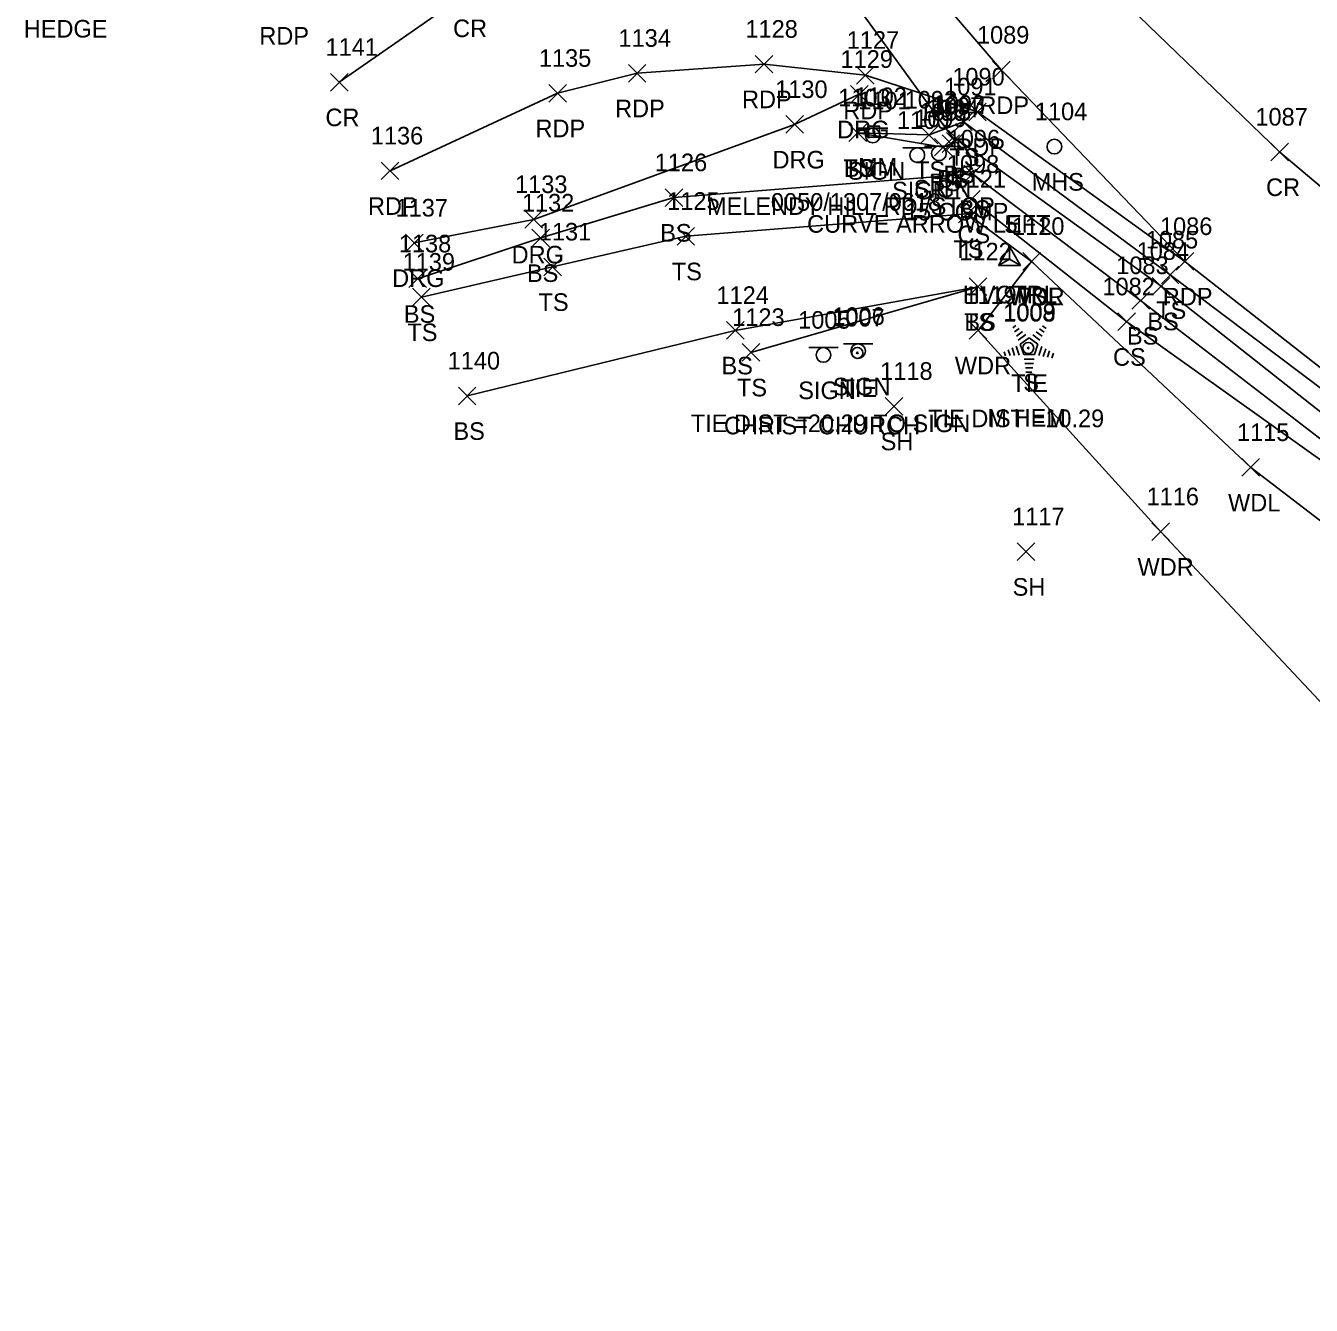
# Model space of a CAD drawing. Extents: x 1620157 to 1620595, y 115111 to 117885.
# Drawn here: x 1620296.4 to 1620442.4, y 115116.1 to 115261.5 of the extents above; entities that cross this region are included whole.
import ezdxf

# ---------------------------------------------------------------- set-up
doc = ezdxf.new("R2010")
doc.units = 0
for name, color, linetype in [('C_A', 7, 'Continuous'), ('C_C', 7, 'Continuous'), ('C_I', 7, 'Continuous'), ('CBP', 7, 'Continuous'), ('CPSM', 7, 'Continuous'), ('D_A', 7, 'Continuous'), ('D_C', 7, 'Continuous'), ('D_I', 7, 'Continuous'), ('D_TIC', 7, 'Continuous'), ('DCP', 7, 'Continuous'), ('L_A', 7, 'Continuous'), ('L_C', 7, 'Continuous'), ('L_I', 7, 'Continuous'), ('L_TIC', 7, 'Continuous'), ('LAWA', 7, 'Continuous'), ('LELB', 7, 'Continuous'), ('LTC', 7, 'Continuous'), ('P_A', 7, 'Continuous'), ('P_I', 7, 'Continuous'), ('P_TIC', 7, 'Continuous'), ('PET', 7, 'Continuous'), ('PRC', 7, 'Continuous'), ('R_A', 7, 'Continuous'), ('R_I', 7, 'Continuous'), ('R_TIC', 7, 'Continuous'), ('RDG', 7, 'Continuous'), ('S_A', 7, 'Continuous'), ('S_C', 7, 'Continuous'), ('S_I', 7, 'Continuous'), ('SRM', 7, 'Continuous'), ('SSGN', 7, 'Continuous'), ('U_A', 7, 'Continuous'), ('U_I', 7, 'Continuous'), ('USMH', 7, 'Continuous')]:
    doc.layers.add(name, color=color, linetype=linetype)

msp = doc.modelspace()

# ---------------------------------------------------------------- linework, layer by layer
at = {"layer": 'CBP'}
for centre, radius in [((1620390.83, 115224.31), 0.625), ((1620390.83, 115224.31), 0.0833), ((1620410.24, 115224.87), 0.625), ((1620410.24, 115224.87), 0.0833)]:
    msp.add_circle(centre, radius, dxfattribs=at)
at = {"layer": 'CPSM'}
for p, q in [((1620406.86, 115234.22), (1620408.11, 115236.39)), ((1620409.36, 115234.22), (1620408.11, 115236.39)), ((1620408.11, 115234.94), (1620408.11, 115236.39)), ((1620406.86, 115234.22), (1620408.11, 115234.94)), ((1620408.11, 115234.94), (1620408.11, 115234.94)), ((1620408.11, 115234.94), (1620409.36, 115234.22)), ((1620406.86, 115234.22), (1620409.36, 115234.22))]:
    msp.add_line(p, q, dxfattribs=at)
at = {"layer": 'D_TIC'}
for points in [[(1620400.96, 115247.35), (1620402.96, 115249.35)], [(1620402.96, 115247.35), (1620400.96, 115249.35)]]:
    msp.add_lwpolyline(points, dxfattribs=at)
at = {"layer": 'DCP'}
msp.add_lwpolyline([(1620401.96, 115248.35), (1620331.92, 115344.78)], dxfattribs=at)
at = {"layer": 'L_TIC'}
for points in [[(1620401.89, 115249.56), (1620403.89, 115251.56)], [(1620403.89, 115249.56), (1620401.89, 115251.56)], [(1620389.86, 115248.31), (1620391.86, 115250.31)], [(1620391.86, 115248.31), (1620389.86, 115250.31)], [(1620389.86, 115248.31), (1620391.86, 115250.31)], [(1620391.86, 115248.31), (1620389.86, 115250.31)], [(1620397.98, 115248.07), (1620399.98, 115250.07)], [(1620399.98, 115248.07), (1620397.98, 115250.07)], [(1620400.45, 115247.07), (1620402.45, 115249.07)], [(1620402.45, 115247.07), (1620400.45, 115249.07)], [(1620401.18, 115247.57), (1620403.18, 115249.57)], [(1620403.18, 115247.57), (1620401.18, 115249.57)], [(1620399.59, 115246.68), (1620401.59, 115248.68)], [(1620401.59, 115246.68), (1620399.59, 115248.68)], [(1620402.93, 115243.65), (1620404.93, 115245.65)], [(1620404.93, 115243.65), (1620402.93, 115245.65)], [(1620369, 115240.95), (1620371, 115242.95)], [(1620371, 115240.95), (1620369, 115242.95)], [(1620402.77, 115240.77), (1620404.77, 115242.77)], [(1620404.77, 115240.77), (1620402.77, 115242.77)], [(1620402.33, 115239.09), (1620404.33, 115241.09)], [(1620404.33, 115239.09), (1620402.33, 115241.09)], [(1620353.86, 115236.37), (1620355.86, 115238.37)], [(1620355.86, 115236.37), (1620353.86, 115238.37)], [(1620370.35, 115236.56), (1620372.35, 115238.56)], [(1620372.35, 115236.56), (1620370.35, 115238.56)], [(1620355.21, 115233.08), (1620357.21, 115235.08)], [(1620357.21, 115233.08), (1620355.21, 115235.08)], [(1620409.63, 115233.71), (1620411.63, 115235.71)], [(1620411.63, 115233.71), (1620409.63, 115235.71)], [(1620409.63, 115233.71), (1620411.63, 115235.71)], [(1620411.63, 115233.71), (1620409.63, 115235.71)], [(1620409.63, 115233.71), (1620411.63, 115235.71)], [(1620411.63, 115233.71), (1620409.63, 115235.71)], [(1620339.88, 115231.73), (1620341.88, 115233.73)], [(1620341.88, 115231.73), (1620339.88, 115233.73)], [(1620425.37, 115232.17), (1620427.37, 115234.17)], [(1620427.37, 115232.17), (1620425.37, 115234.17)], [(1620340.31, 115229.65), (1620342.31, 115231.65)], [(1620342.31, 115229.65), (1620340.31, 115231.65)], [(1620403.55, 115230.82), (1620405.55, 115232.82)], [(1620405.55, 115230.82), (1620403.55, 115232.82)], [(1620403.55, 115230.82), (1620405.55, 115232.82)], [(1620405.55, 115230.82), (1620403.55, 115232.82)], [(1620424.33, 115230.88), (1620426.33, 115232.88)], [(1620426.33, 115230.88), (1620424.33, 115232.88)], [(1620422.01, 115229.26), (1620424.01, 115231.26)], [(1620424.01, 115229.26), (1620422.01, 115231.26)], [(1620420.44, 115226.85), (1620422.44, 115228.85)], [(1620422.44, 115226.85), (1620420.44, 115228.85)], [(1620375.96, 115225.87), (1620377.96, 115227.87)], [(1620377.96, 115225.87), (1620375.96, 115227.87)], [(1620403.55, 115225.87), (1620405.55, 115227.87)], [(1620405.55, 115225.87), (1620403.55, 115227.87)], [(1620377.75, 115223.37), (1620379.75, 115225.37)], [(1620379.75, 115223.37), (1620377.75, 115225.37)], [(1620345.51, 115218.43), (1620347.51, 115220.43)], [(1620347.51, 115218.43), (1620345.51, 115220.43)], [(1620393.99, 115217.25), (1620395.99, 115219.25)], [(1620395.99, 115217.25), (1620393.99, 115219.25)], [(1620434.52, 115210.3), (1620436.52, 115212.3)], [(1620436.52, 115210.3), (1620434.52, 115212.3)], [(1620424.3, 115203), (1620426.3, 115205)], [(1620426.3, 115203), (1620424.3, 115205)], [(1620408.98, 115200.73), (1620410.98, 115202.73)], [(1620410.98, 115200.73), (1620408.98, 115202.73)]]:
    msp.add_lwpolyline(points, dxfattribs=at)
at = {"layer": 'LAWA'}
for points in [[(1620547.83, 115116.13), (1620521.54, 115127.07), (1620480.9, 115160.38), (1620453.76, 115173.69), (1620425.3, 115204), (1620404.55, 115226.87), (1620410.63, 115234.71)], [(1620557.01, 115131.08), (1620520.13, 115153.23), (1620496.39, 115166.83), (1620458.33, 115193.85), (1620435.52, 115211.3), (1620410.63, 115234.71)]]:
    msp.add_lwpolyline(points, dxfattribs=at)
at = {"layer": 'LELB'}
for points in [[(1620561.51, 115138.96), (1620534.96, 115155.05), (1620507.65, 115174.47), (1620478.57, 115195.13), (1620450.29, 115215.14), (1620426.37, 115233.17), (1620402.89, 115250.56), (1620398.98, 115249.07), (1620390.86, 115249.31)], [(1620561.16, 115138.52), (1620534.84, 115154.5), (1620507.17, 115173.96), (1620477.85, 115194.31), (1620448.7, 115213.47), (1620425.33, 115231.88), (1620402.18, 115248.57), (1620401.45, 115248.07), (1620400.59, 115247.68), (1620390.86, 115249.31)], [(1620560.42, 115137.14), (1620534.09, 115153.34), (1620505.73, 115171.81), (1620476.58, 115192.31), (1620447.1, 115211.71), (1620423.01, 115230.26), (1620403.93, 115244.65), (1620370, 115241.95), (1620354.86, 115237.37), (1620340.88, 115232.73)], [(1620559.1, 115135.33), (1620533.32, 115151.76), (1620504.7, 115169.78), (1620474.68, 115190.6), (1620444.93, 115211.09), (1620421.44, 115227.85), (1620403.77, 115241.77)], [(1620410.63, 115234.71), (1620403.33, 115240.09), (1620371.35, 115237.56), (1620356.21, 115234.08), (1620341.31, 115230.65)], [(1620404.55, 115231.82), (1620376.96, 115226.87), (1620346.51, 115219.43)], [(1620404.55, 115231.82), (1620378.75, 115224.37)]]:
    msp.add_lwpolyline(points, dxfattribs=at)
at = {"layer": 'LTC'}
for p, q in [((1620408.49, 115227.16), (1620408.84, 115227.41)), ((1620408.69, 115226.69), (1620409.22, 115227.07)), ((1620411.51, 115227.05), (1620412.06, 115226.65)), ((1620411.88, 115227.4), (1620412.3, 115227.09)), ((1620408.9, 115226.22), (1620409.61, 115226.74)), ((1620409.11, 115225.76), (1620409.99, 115226.4)), ((1620409.34, 115225.3), (1620410.35, 115226.04)), ((1620410.35, 115226.04), (1620411.35, 115225.31)), ((1620410.77, 115226.35), (1620411.58, 115225.76)), ((1620411.14, 115226.7), (1620411.82, 115226.21)), ((1620407.52, 115224.44), (1620407.67, 115223.97)), ((1620407.97, 115224.65), (1620408.18, 115224)), ((1620408.43, 115224.87), (1620408.7, 115224.03)), ((1620408.88, 115225.08), (1620409.21, 115224.07)), ((1620409.34, 115225.3), (1620409.73, 115224.11)), ((1620411.35, 115225.31), (1620410.96, 115224.11)), ((1620411.78, 115225.04), (1620411.45, 115224)), ((1620412.23, 115224.79), (1620411.94, 115223.91)), ((1620412.67, 115224.54), (1620412.44, 115223.81)), ((1620413.12, 115224.29), (1620412.93, 115223.72)), ((1620410.96, 115224.11), (1620409.73, 115224.11)), ((1620410.92, 115223.61), (1620409.77, 115223.61)), ((1620410.83, 115223.11), (1620409.85, 115223.11)), ((1620410.75, 115222.61), (1620409.92, 115222.61)), ((1620410.67, 115222.11), (1620409.99, 115222.11))]:
    msp.add_line(p, q, dxfattribs=at)
at = {"layer": 'P_TIC'}
for points in [[(1620379.24, 115256.11), (1620381.24, 115258.11)], [(1620381.24, 115256.11), (1620379.24, 115258.11)], [(1620364.82, 115255.08), (1620366.82, 115257.08)], [(1620366.82, 115255.08), (1620364.82, 115257.08)], [(1620390.75, 115254.85), (1620392.75, 115256.85)], [(1620392.75, 115254.85), (1620390.75, 115256.85)], [(1620406.2, 115255.44), (1620408.2, 115257.44)], [(1620408.2, 115255.44), (1620406.2, 115257.44)], [(1620330.98, 115254.06), (1620332.98, 115256.06)], [(1620332.98, 115254.06), (1620330.98, 115256.06)], [(1620355.78, 115252.81), (1620357.78, 115254.81)], [(1620357.78, 115252.81), (1620355.78, 115254.81)], [(1620403.48, 115250.68), (1620405.48, 115252.68)], [(1620405.48, 115250.68), (1620403.48, 115252.68)], [(1620437.82, 115246.13), (1620439.82, 115248.13)], [(1620439.82, 115246.13), (1620437.82, 115248.13)], [(1620336.75, 115243.99), (1620338.75, 115245.99)], [(1620338.75, 115243.99), (1620336.75, 115245.99)], [(1620427.04, 115233.7), (1620429.04, 115235.7)], [(1620429.04, 115233.7), (1620427.04, 115235.7)], [(1620427.04, 115233.7), (1620429.04, 115235.7)], [(1620429.04, 115233.7), (1620427.04, 115235.7)]]:
    msp.add_lwpolyline(points, dxfattribs=at)
at = {"layer": 'PET'}
for points in [[(1620562.04, 115139.54), (1620535.96, 115156.9), (1620508.49, 115175.94), (1620479.2, 115196.11), (1620451.1, 115216.62), (1620428.04, 115234.7), (1620407.2, 115256.44), (1620380.21, 115287.87), (1620366.18, 115309.19), (1620356.59, 115324.56), (1620350.49, 115341.93), (1620344.69, 115361.16), (1620336.51, 115388.61), (1620345.69, 115391.55), (1620355.3, 115394.86)], [(1620428.04, 115234.7), (1620404.48, 115251.68), (1620391.75, 115255.85), (1620380.24, 115257.11), (1620365.82, 115256.08), (1620356.78, 115253.81), (1620337.75, 115244.99)]]:
    msp.add_lwpolyline(points, dxfattribs=at)
at = {"layer": 'PRC'}
for points in [[(1620569.19, 115149.92), (1620542.76, 115168.02), (1620512.11, 115189.58), (1620491.05, 115205.01), (1620469.11, 115221.78), (1620461.73, 115227.82), (1620438.82, 115247.13), (1620418.59, 115266.65), (1620405.03, 115281.95), (1620392.88, 115297.86), (1620380.47, 115316.24), (1620370.64, 115332.81), (1620355.49, 115365.23), (1620348.1, 115384.58), (1620345.69, 115391.55)], [(1620331.98, 115255.06), (1620346.47, 115265.18), (1620365.55, 115277.69), (1620370.36, 115280.84), (1620377.45, 115285.52), (1620380.21, 115287.87)]]:
    msp.add_lwpolyline(points, dxfattribs=at)
at = {"layer": 'R_TIC'}
for points in [[(1620390.05, 115252.69), (1620392.05, 115254.69)], [(1620392.05, 115252.69), (1620390.05, 115254.69)], [(1620382.71, 115249.26), (1620384.71, 115251.26)], [(1620384.71, 115249.26), (1620382.71, 115251.26)], [(1620353.07, 115238.47), (1620355.07, 115240.47)], [(1620355.07, 115238.47), (1620353.07, 115240.47)], [(1620339.5, 115235.8), (1620341.5, 115237.8)], [(1620341.5, 115235.8), (1620339.5, 115237.8)]]:
    msp.add_lwpolyline(points, dxfattribs=at)
at = {"layer": 'RDG'}
msp.add_lwpolyline([(1620391.05, 115253.69), (1620383.71, 115250.26), (1620354.07, 115239.47), (1620340.5, 115236.8)], dxfattribs=at)
at = {"layer": 'SRM'}
msp.add_lwpolyline([(1620392.09, 115250.08), (1620393.34, 115250.08), (1620393.34, 115248.83), (1620392.09, 115248.83)], close=True, dxfattribs=at)
msp.add_circle((1620392.71, 115249.46), 0.0833, dxfattribs=at)
at = {"layer": 'SSGN'}
for p, q in [((1620390.95, 115249.83), (1620394.28, 115249.83)), ((1620392.59, 115249), (1620392.59, 115249)), ((1620395.99, 115247.6), (1620399.33, 115247.6)), ((1620398.45, 115247.81), (1620401.79, 115247.81)), ((1620397.64, 115246.77), (1620397.64, 115246.77)), ((1620400.1, 115246.98), (1620400.1, 115246.98)), ((1620385.33, 115224.91), (1620388.66, 115224.91)), ((1620389.27, 115225.34), (1620392.61, 115225.34)), ((1620390.92, 115224.51), (1620390.92, 115224.51)), ((1620386.98, 115224.08), (1620386.98, 115224.08))]:
    msp.add_line(p, q, dxfattribs=at)
for centre in [(1620392.59, 115249), (1620397.64, 115246.77), (1620400.1, 115246.98), (1620386.98, 115224.08), (1620390.92, 115224.51)]:
    msp.add_circle(centre, 0.833, dxfattribs=at)
at = {"layer": 'USMH'}
for p, q in [((1620413.21, 115247.74), (1620413.21, 115247.74)), ((1620414.04, 115247.74), (1620414.04, 115247.74))]:
    msp.add_line(p, q, dxfattribs=at)
msp.add_circle((1620413.21, 115247.74), 0.833, dxfattribs=at)

# ---------------------------------------------------------------- texts
at = {"layer": 'C_A'}
for s, p in [('HVCTRL', (1620402.81, 115229.94)), ('TIE', (1620388.91, 115219.31)), ('TIE', (1620408.32, 115219.87))]:
    msp.add_text(s, height=2, dxfattribs=at).set_placement(p)
at = {"layer": 'C_C'}
for s, p in [('TIE DIST =20.29 TO SIGN', (1620371.91, 115215.31)), ('TIE DIST =10.29', (1620398.88, 115215.87))]:
    msp.add_text(s, height=2, dxfattribs=at).set_placement(p)
at = {"layer": 'C_I'}
for s, p in [('5', (1620407.55, 115237.94)), ('1007', (1620387.98, 115227.31)), ('1008', (1620407.39, 115227.87))]:
    msp.add_text(s, height=2, dxfattribs=at).set_placement(p)
at = {"layer": 'D_A'}
msp.add_text('P', height=2, dxfattribs=at).set_placement((1620401.34, 115243.35))
at = {"layer": 'D_C'}
msp.add_text('15 CGMP', height=2, dxfattribs=at).set_placement((1620396.25, 115239.35))
at = {"layer": 'D_I'}
msp.add_text('1097', height=2, dxfattribs=at).set_placement((1620399.19, 115251.35))
at = {"layer": 'L_A'}
for s, p in [('HEDGE', (1620296.14, 115260.13)), ('TS', (1620401.3, 115245.56)), ('TS', (1620389.27, 115244.31)), ('BS', (1620389.3, 115244.31)), ('TS', (1620397.39, 115244.07)), ('BS', (1620399.03, 115242.68)), ('BS', (1620399.89, 115243.07)), ('BS', (1620400.62, 115243.57)), ('BS', (1620402.37, 115239.65)), ('BS', (1620368.44, 115236.95)), ('CS', (1620402.21, 115236.77)), ('TS', (1620401.74, 115235.09)), ('BS', (1620353.3, 115232.37)), ('TS', (1620369.76, 115232.56)), ('WDR', (1620407.99, 115229.71)), ('WDL', (1620408.04, 115229.71)), ('TS', (1620409.04, 115229.71)), ('TS', (1620354.62, 115229.08)), ('TS', (1620424.78, 115228.17)), ('BS', (1620339.32, 115227.73)), ('TS', (1620402.96, 115226.82)), ('BS', (1620402.99, 115226.82)), ('BS', (1620423.77, 115226.88)), ('TS', (1620339.72, 115225.65)), ('BS', (1620421.46, 115225.26)), ('CS', (1620419.88, 115222.85)), ('BS', (1620375.4, 115221.87)), ('WDR', (1620401.91, 115221.87)), ('TS', (1620377.16, 115219.37)), ('S', (1620409.68, 115219.95)), ('BS', (1620344.95, 115214.43)), ('SH', (1620393.48, 115213.25)), ('WDL', (1620432.94, 115206.3)), ('WDR', (1620422.66, 115199)), ('SH', (1620408.47, 115196.73))]:
    msp.add_text(s, height=2, dxfattribs=at).set_placement(p)
at = {"layer": 'L_C'}
msp.add_text('M HEM', height=2, dxfattribs=at).set_placement((1620405.61, 115215.95))
at = {"layer": 'L_I'}
for s, p in [('1091', (1620400.69, 115253.56)), ('1103', (1620388.66, 115252.31)), ('1103', (1620388.66, 115252.31)), ('1092', (1620396.21, 115252.07)), ('1093', (1620399.41, 115251.57)), ('1095', (1620397.82, 115250.68)), ('1094', (1620398.67, 115251.07)), ('1096', (1620401.1, 115247.65)), ('1126', (1620367.82, 115244.95)), ('1098', (1620401, 115244.77)), ('1121', (1620401.77, 115243.09)), ('1132', (1620352.73, 115240.37)), ('1125', (1620369.23, 115240.56)), ('1131', (1620354.65, 115237.08)), ('1120', (1620408.41, 115237.71)), ('1120', (1620408.41, 115237.71)), ('1120', (1620408.41, 115237.71)), ('1138', (1620338.75, 115235.73)), ('1085', (1620423.6, 115236.17)), ('1122', (1620402.42, 115234.82)), ('1122', (1620402.42, 115234.82)), ('1084', (1620422.56, 115234.88)), ('1139', (1620339.18, 115233.65)), ('1083', (1620420.24, 115233.26)), ('1124', (1620374.83, 115229.87)), ('1119', (1620402.98, 115229.87)), ('1082', (1620418.67, 115230.85)), ('1009', (1620407.43, 115227.95)), ('1123', (1620376.62, 115227.37)), ('1140', (1620344.3, 115222.43)), ('1118', (1620393.43, 115221.25)), ('1115', (1620433.96, 115214.3)), ('1116', (1620423.69, 115207)), ('1117', (1620408.42, 115204.73))]:
    msp.add_text(s, height=2, dxfattribs=at).set_placement(p)
at = {"layer": 'LTC'}
msp.add_text('.', height=1.04, rotation=270, dxfattribs=at).set_placement((1620410.23, 115225.05))
at = {"layer": 'P_A'}
for s, p in [('CR', (1620344.91, 115260.18)), ('RDP', (1620322.9, 115259.33)), ('RDP', (1620377.73, 115252.11)), ('RDP', (1620404.69, 115251.44)), ('CR', (1620330.41, 115250.06)), ('RDP', (1620363.31, 115251.08)), ('RDP', (1620389.24, 115250.85)), ('RDP', (1620354.27, 115248.81)), ('RDP', (1620401.96, 115246.68)), ('CR', (1620437.26, 115242.13)), ('RDP', (1620335.24, 115239.99)), ('RDP', (1620425.53, 115229.7)), ('RDP', (1620425.53, 115229.7))]:
    msp.add_text(s, height=2, dxfattribs=at).set_placement(p)
at = {"layer": 'P_I'}
for s, p in [('1128', (1620378.12, 115260.11)), ('1134', (1620363.7, 115259.08)), ('1127', (1620389.63, 115258.85)), ('1089', (1620404.42, 115259.44)), ('1141', (1620330.42, 115258.06)), ('1135', (1620354.66, 115256.81)), ('1090', (1620401.62, 115254.68)), ('1087', (1620436.05, 115250.13)), ('1136', (1620335.57, 115247.99)), ('1086', (1620425.21, 115237.7)), ('1086', (1620425.21, 115237.7))]:
    msp.add_text(s, height=2, dxfattribs=at).set_placement(p)
at = {"layer": 'R_A'}
for p in [(1620388.54, 115248.69), (1620381.2, 115245.26), (1620351.56, 115234.47), (1620337.99, 115231.8)]:
    msp.add_text('DRG', height=2, dxfattribs=at).set_placement(p)
at = {"layer": 'R_I'}
for s, p in [('1129', (1620388.92, 115256.69)), ('1130', (1620381.5, 115253.26)), ('1133', (1620351.95, 115242.47)), ('1137', (1620338.38, 115239.8))]:
    msp.add_text(s, height=2, dxfattribs=at).set_placement(p)
at = {"layer": 'S_A'}
for s, p in [('MM', (1620390.9, 115244.46)), ('SIGN', (1620389.73, 115243.98)), ('SIGN', (1620394.78, 115241.75)), ('SIGN', (1620397.24, 115241.96)), ('SIGN', (1620388.06, 115219.49)), ('SIGN', (1620384.12, 115219.06))]:
    msp.add_text(s, height=2, dxfattribs=at).set_placement(p)
at = {"layer": 'S_C'}
for s, p in [('MELENDY HILL RD /STOP', (1620373.75, 115239.98)), ('0050/1307/0618', (1620381.01, 115240.46)), ('CURVE ARROW LEFT', (1620385.13, 115237.96)), ('CHRIST CHURCH', (1620375.68, 115215.06))]:
    msp.add_text(s, height=2, dxfattribs=at).set_placement(p)
at = {"layer": 'S_I'}
for s, p in [('1102', (1620390.51, 115252.46)), ('1101', (1620390.94, 115251.98)), ('1099', (1620397.3, 115249.96)), ('1100', (1620395.33, 115249.75)), ('1005', (1620384.11, 115227.06)), ('1006', (1620388, 115227.49))]:
    msp.add_text(s, height=2, dxfattribs=at).set_placement(p)
at = {"layer": 'U_A'}
msp.add_text('MHS', height=2, dxfattribs=at).set_placement((1620410.63, 115242.74))
at = {"layer": 'U_I'}
msp.add_text('1104', height=2, dxfattribs=at).set_placement((1620411, 115250.74))

doc.saveas('drawing.dxf')
